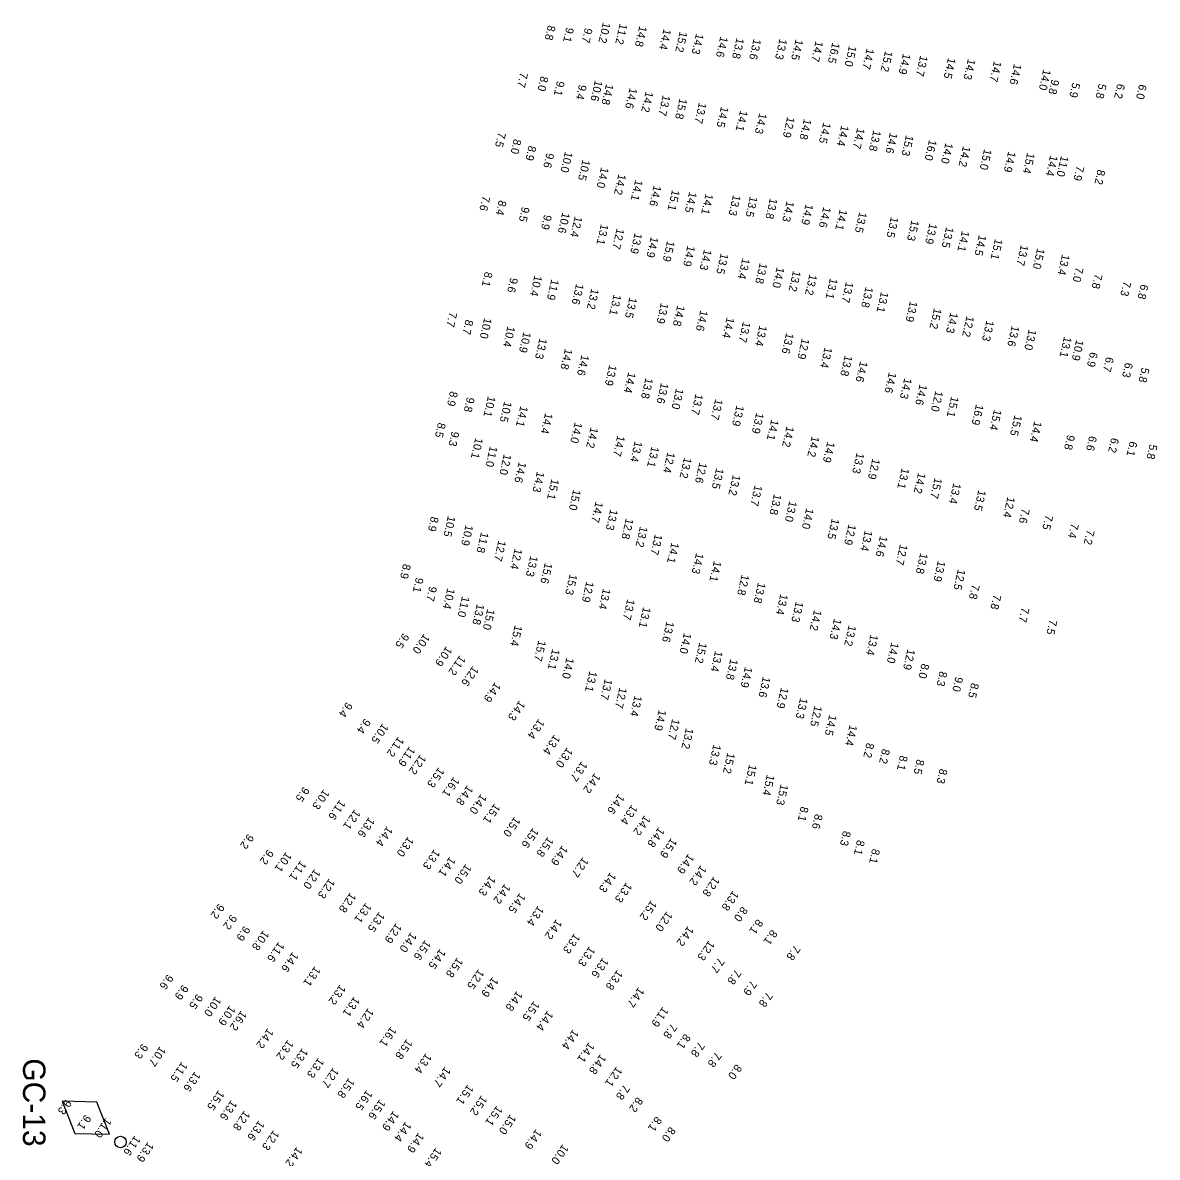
# Model space of a CAD drawing. Extents: x 815385 to 820851, y 582449 to 604245.
# Drawn here: x 820142 to 820851, y 589394 to 590103 of the extents above; entities that cross this region are included whole.
import ezdxf

# ---------------------------------------------------------------- set-up
doc = ezdxf.new("R2010")
doc.units = 0
for name, color, linetype in [('V-CHAN-AIDS', 7, 'Continuous'), ('V-TOPO-SOUN-021309', 7, 'Continuous'), ('V-TOPO-SOUN-EXCSS', 7, 'Continuous')]:
    doc.layers.add(name, color=color, linetype=linetype)

msp = doc.modelspace()

# ---------------------------------------------------------------- linework, layer by layer
at = {"layer": 'V-CHAN-AIDS'}
msp.add_lwpolyline([(820196.31, 589408.18), (820188.45, 589428.33), (820166.82, 589428.83), (820174.68, 589408.67)], close=True, dxfattribs=at)
msp.add_circle((820203.19, 589403.36), 3.6, dxfattribs=at)

# ---------------------------------------------------------------- texts
msp.add_text('GC-13', height=14, rotation=270, dxfattribs=at).set_placement((820142.31, 589455.63))
at = {"layer": 'V-TOPO-SOUN-021309'}
for s, rotation, p in [('10.2 ', 257.192, (820504.72, 590103.28)), ('11.2 ', 257.192, (820515.25, 590102.47)), ('8.8', 257.192, (820470.37, 590101.49)), ('9.1', 257.192, (820481.83, 590100.14)), ('9.7', 257.192, (820493.45, 590099.81)), ('14.8 ', 257.192, (820527.55, 590101)), ('14.4 ', 257.192, (820542.67, 590099.18)), ('15.2 ', 257.192, (820552.74, 590097.55)), ('14.3 ', 257.192, (820562.97, 590096.27)), ('14.6 ', 257.192, (820578.13, 590094.42)), ('13.8 ', 257.192, (820588.26, 590093.52)), ('13.6 ', 257.192, (820598.89, 590092.94)), ('13.3 ', 257.192, (820615.12, 590093.01)), ('14.5 ', 257.192, (820625.15, 590092.64)), ('14.7 ', 257.192, (820637.67, 590091.61)), ('16.5 ', 257.192, (820648.09, 590090.64)), ('15.0 ', 257.192, (820658.53, 590088.6)), ('14.7 ', 257.192, (820669.55, 590086.94)), ('15.2 ', 257.192, (820681.09, 590085.41)), ('14.9 ', 257.192, (820692.26, 590083.79)), ('13.7 ', 257.192, (820703.03, 590082.55)), ('14.5 ', 257.192, (820720.46, 590081.11)), ('14.3 ', 257.192, (820732.84, 590080.42)), ('14.7 ', 257.192, (820749.14, 590079.1)), ('14.6 ', 257.192, (820761.63, 590077.37)), ('7.7', 257.192, (820453.08, 590071.97)), ('8.0', 257.192, (820465.87, 590069.67)), ('10.6 ', 257.192, (820499.76, 590067.02)), ('14.0 ', 257.192, (820779.94, 590073.87)), ('9.8', 257.192, (820785.11, 590067.67)), ('9.1', 257.192, (820476.03, 590066.69)), ('9.4', 257.192, (820489.81, 590064.4)), ('14.8 ', 257.192, (820506.68, 590064.77)), ('14.6 ', 257.192, (820521.45, 590062.32)), ('14.2 ', 257.192, (820531.47, 590060.08)), ('5.9', 257.192, (820798.16, 590065.62)), ('5.8', 257.192, (820814.62, 590065.01)), ('6.2', 257.192, (820826.17, 590064.97)), ('6.0', 257.192, (820839.86, 590064.56)), ('13.7 ', 257.192, (820542.13, 590057.84)), ('15.8 ', 257.192, (820552.63, 590055.73)), ('13.7 ', 257.192, (820564.74, 590053.12)), ('14.5 ', 257.192, (820578.55, 590050.61)), ('14.1 ', 257.192, (820590.5, 590048.22)), ('14.3 ', 257.192, (820602.46, 590046.56)), ('12.9 ', 257.192, (820619.92, 590044.2)), ('14.8 ', 257.192, (820630.36, 590042.95)), ('14.5 ', 257.192, (820642.47, 590040.66)), ('14.4 ', 257.192, (820653.72, 590038.9)), ('7.5', 257.192, (820439.29, 590034.58)), ('14.7 ', 257.192, (820663.67, 590037.29)), ('13.8 ', 257.192, (820673.75, 590035.81)), ('14.6 ', 257.192, (820684.11, 590034.33)), ('15.3 ', 257.192, (820694.14, 590032.77)), ('8.0', 257.192, (820449, 590030.38)), ('8.9', 257.192, (820458.3, 590026.22)), ('16.0 ', 257.192, (820708.58, 590029.91)), ('14.0 ', 257.192, (820718.8, 590027.99)), ('14.2 ', 257.192, (820729.77, 590025.98)), ('9.6', 257.192, (820469.42, 590021.68)), ('10.0 ', 257.192, (820481.06, 590022.45)), ('10.5 ', 257.192, (820492, 590017.47)), ('15.0 ', 257.192, (820742.99, 590024.1)), ('14.9 ', 257.192, (820758.04, 590022.59)), ('15.4 ', 257.192, (820769.9, 590021.77)), ('14.4 ', 257.192, (820784.25, 590020.17)), ('11.0 ', 257.192, (820791.03, 590019.86)), ('14.0 ', 257.192, (820503.64, 590012.72)), ('7.9', 257.192, (820800.7, 590013.64)), ('8.2', 257.192, (820813.91, 590011.31)), ('14.2 ', 257.192, (820514.46, 590008.45)), ('14.1 ', 257.192, (820524.95, 590004.84)), ('14.6 ', 257.192, (820536.51, 590001.38)), ('15.1 ', 257.192, (820547.97, 589998.61)), ('14.5 ', 257.192, (820558.71, 589997.35)), ('14.1 ', 257.192, (820568.94, 589996.2)), ('7.6', 257.192, (820429.52, 589994.87)), ('8.4', 257.192, (820439.72, 589992.1)), ('13.3 ', 257.192, (820586.08, 589995.44)), ('13.5 ', 257.192, (820596.64, 589994.55)), ('13.8 ', 257.192, (820609.11, 589993.38)), ('14.3 ', 257.192, (820619.58, 589991.6)), ('14.9 ', 257.192, (820631.43, 589989.71)), ('9.5', 257.192, (820454.15, 589988.06)), ('9.9', 257.192, (820468.02, 589983.1)), ('10.6 ', 257.192, (820479.36, 589984.46)), ('12.4 ', 257.192, (820487.14, 589982.08)), ('14.6 ', 257.192, (820642.5, 589987.97)), ('14.1 ', 257.192, (820652.74, 589986.37)), ('13.5 ', 257.192, (820664.97, 589984.74)), ('13.5 ', 257.192, (820684.72, 589981.74)), ('13.1 ', 257.192, (820503.52, 589977.21)), ('15.3 ', 257.192, (820697.58, 589979.69)), ('13.9 ', 257.192, (820708.85, 589977.69)), ('13.5 ', 257.192, (820719.22, 589975.4)), ('12.7 ', 257.192, (820513.35, 589974.53)), ('13.9 ', 257.192, (820524.58, 589971.65)), ('14.9 ', 257.192, (820534.67, 589969.26)), ('14.1 ', 257.192, (820729.08, 589972.99)), ('14.5 ', 257.192, (820739.72, 589970.4)), ('15.1 ', 257.192, (820749.8, 589968.01)), ('15.9 ', 257.192, (820544.87, 589966.75)), ('14.9 ', 257.192, (820557.58, 589963.74)), ('14.3 ', 257.192, (820567.97, 589961.41)), ('13.7 ', 257.192, (820765.92, 589964.23)), ('15.0 ', 257.192, (820776.12, 589962.12)), ('13.5 ', 257.192, (820578.39, 589958.94)), ('13.4 ', 257.192, (820591.86, 589955.83)), ('13.4 ', 257.192, (820791.71, 589958.33)), ('8.1', 257.192, (820431, 589947.46)), ('13.8 ', 257.192, (820602.74, 589952.95)), ('14.0 ', 257.192, (820613.4, 589950.35)), ('13.2 ', 257.192, (820623.6, 589948.05)), ('7.0', 257.192, (820800.24, 589950.37)), ('9.6', 257.192, (820446.87, 589943.76)), ('10.4 ', 257.192, (820461.98, 589945.16)), ('11.9 ', 257.192, (820472.52, 589942.7)), ('13.6 ', 257.192, (820488.02, 589939.95)), ('13.2 ', 257.192, (820633.81, 589945.8)), ('13.1 ', 257.192, (820646.69, 589943.4)), ('13.7 ', 257.192, (820656.6, 589941.1)), ('7.8', 257.192, (820812.12, 589946.17)), ('7.3', 257.192, (820830.07, 589941.55)), ('6.8', 257.192, (820840.86, 589939.6)), ('13.2 ', 257.192, (820497.52, 589936.91)), ('13.1 ', 257.192, (820511.46, 589933.24)), ('13.8 ', 257.192, (820668.9, 589937.99)), ('13.1 ', 257.192, (820678.52, 589934.93)), ('13.5 ', 257.192, (820521.32, 589931.43)), ('13.9 ', 257.192, (820540.98, 589927.97)), ('14.8 ', 257.192, (820551.24, 589926.43)), ('13.9 ', 257.192, (820696.62, 589929.07)), ('7.7', 257.192, (820408.82, 589922.27)), ('10.0 ', 257.192, (820430.55, 589918.63)), ('14.6 ', 257.192, (820565.64, 589923.38)), ('14.4 ', 257.192, (820582.12, 589918.96)), ('15.2 ', 257.192, (820711.64, 589924.67)), ('14.3 ', 257.192, (820721.93, 589922)), ('12.2 ', 257.192, (820732.02, 589919.77)), ('8.7', 257.192, (820418.93, 589917.52)), ('10.4 ', 257.192, (820445.1, 589913.44)), ('13.7 ', 257.192, (820592.27, 589916.21)), ('13.4 ', 257.192, (820602.56, 589913.88)), ('13.3 ', 257.192, (820744.46, 589917.02)), ('13.6 ', 257.192, (820760.24, 589913.69)), ('13.0 ', 257.192, (820770.88, 589911.46)), ('10.9 ', 257.192, (820455.08, 589909.83)), ('13.3 ', 257.192, (820465.11, 589905.87)), ('13.6 ', 257.192, (820619.25, 589909.21)), ('12.9 ', 257.192, (820629.09, 589905.77)), ('13.1 ', 257.192, (820792.91, 589906.87)), ('10.9 ', 257.192, (820800.5, 589904.88)), ('14.8 ', 257.192, (820481, 589899.35)), ('13.4 ', 257.192, (820643.33, 589900.28)), ('6.9', 257.192, (820809.19, 589897.27)), ('14.6 ', 257.192, (820491.35, 589895.52)), ('13.8 ', 257.192, (820655.89, 589895.21)), ('14.6 ', 257.192, (820665.48, 589891.52)), ('6.7', 257.192, (820819.18, 589894.22)), ('6.3', 257.192, (820831.16, 589890.69)), ('13.9 ', 257.192, (820508.7, 589889.22)), ('14.4 ', 257.192, (820520.58, 589884.61)), ('14.6 ', 257.192, (820683.46, 589884.62)), ('5.8', 257.192, (820841.45, 589887.62)), ('13.8 ', 257.192, (820531.34, 589881.09)), ('13.6 ', 257.192, (820541.02, 589877.99)), ('14.3 ', 257.192, (820693.1, 589880.96)), ('14.6 ', 257.192, (820702.65, 589877.06)), ('8.9', 257.192, (820409.28, 589872.79)), ('9.8', 257.192, (820419.78, 589869.12)), ('10.1 ', 257.192, (820432.89, 589869.73)), ('13.0 ', 257.192, (820550.43, 589874.53)), ('13.7 ', 257.192, (820562.62, 589871.1)), ('12.0 ', 257.192, (820712.54, 589873.03)), ('15.1 ', 257.192, (820722.4, 589869.54)), ('10.5 ', 257.192, (820443.06, 589866.39)), ('14.1 ', 257.192, (820453.18, 589863.53)), ('13.7 ', 257.192, (820574.95, 589867.9)), ('13.9 ', 257.192, (820588.21, 589863.94)), ('16.9 ', 257.192, (820737.9, 589864.59)), ('15.4 ', 257.192, (820749.16, 589861.38)), ('14.4 ', 257.192, (820468.62, 589859.16)), ('13.9 ', 257.192, (820600.55, 589859.31)), ('14.1 ', 257.192, (820609.92, 589855.08)), ('15.5 ', 257.192, (820761.95, 589857.86)), ('8.5', 257.192, (820401.73, 589853.17)), ('9.3', 257.192, (820410.18, 589847.74)), ('14.0 ', 257.192, (820487.1, 589853.34)), ('14.2 ', 257.192, (820497.06, 589850.22)), ('14.2 ', 257.192, (820619.5, 589850.86)), ('14.4 ', 257.192, (820774.3, 589853.99)), ('10.1 ', 257.192, (820425.04, 589843.67)), ('14.7 ', 257.192, (820513.79, 589845.04)), ('13.4 ', 257.192, (820524.62, 589841.57)), ('14.2 ', 257.192, (820635.27, 589844.69)), ('14.9 ', 257.192, (820644.95, 589841.18)), ('9.8', 257.192, (820794.92, 589845.53)), ('6.6', 257.192, (820808.66, 589844.89)), ('6.2', 257.192, (820822.43, 589843.7)), ('6.1', 257.192, (820833.91, 589841.48)), ('11.0 ', 257.192, (820434.14, 589838.45)), ('12.0 ', 257.192, (820442.83, 589833.48)), ('13.1 ', 257.192, (820535.13, 589838.25)), ('12.4 ', 257.192, (820545.08, 589834.71)), ('13.3 ', 257.192, (820663.31, 589834.3)), ('5.8', 257.192, (820846.4, 589839.64)), ('14.6 ', 257.192, (820452.16, 589828.58)), ('13.2 ', 257.192, (820555.48, 589831.36)), ('12.6 ', 257.192, (820565.06, 589828.28)), ('12.9 ', 257.192, (820673.15, 589830.7)), ('14.3 ', 257.192, (820463.51, 589822.56)), ('13.5 ', 257.192, (820575.56, 589824.7)), ('13.2 ', 257.192, (820585.95, 589820.57)), ('13.1 ', 257.192, (820691.47, 589824.74)), ('14.2 ', 257.192, (820701.74, 589821.85)), ('15.7 ', 257.192, (820712, 589818.66)), ('15.1 ', 257.192, (820472.61, 589817.99)), ('13.7 ', 257.192, (820599.6, 589814.08)), ('13.4 ', 257.192, (820723.77, 589815.4)), ('15.0 ', 257.192, (820486.21, 589811.36)), ('13.8 ', 257.192, (820611.65, 589808.52)), ('13.5 ', 257.192, (820739.39, 589811.01)), ('12.4 ', 257.192, (820757.55, 589806.79)), ('14.7 ', 257.192, (820500.17, 589803.77)), ('13.3 ', 257.192, (820509.34, 589798.93)), ('13.0 ', 257.192, (820621.23, 589804.16)), ('14.0 ', 257.192, (820631.8, 589799.66)), ('7.6', 257.192, (820766.63, 589799.58)), ('8.9', 257.192, (820397.35, 589794.52)), ('10.5 ', 257.192, (820407.86, 589794.82)), ('12.8 ', 257.192, (820519.12, 589793.35)), ('13.5 ', 257.192, (820647.79, 589793.26)), ('7.5', 257.192, (820781.28, 589795.54)), ('10.9 ', 257.192, (820418.93, 589789.25)), ('11.8 ', 257.192, (820428.59, 589784.73)), ('13.2 ', 257.192, (820527.94, 589788.33)), ('13.7 ', 257.192, (820537.2, 589783.42)), ('12.9 ', 257.192, (820658.26, 589789.62)), ('13.4 ', 257.192, (820668.45, 589785.81)), ('7.4', 257.192, (820797.35, 589790.28)), ('7.2', 257.192, (820807.19, 589786.22)), ('12.7 ', 257.192, (820439.41, 589779.54)), ('14.1 ', 257.192, (820547.58, 589778.27)), ('14.6 ', 257.192, (820677.91, 589782.35)), ('12.7 ', 257.192, (820690.44, 589777.13)), ('12.4 ', 257.192, (820449.61, 589774.47)), ('13.3 ', 257.192, (820459.39, 589769.89)), ('14.3 ', 257.192, (820562.98, 589771.67)), ('13.8 ', 257.192, (820703.08, 589771.64)), ('8.9', 257.192, (820379.92, 589764.94)), ('15.6 ', 257.192, (820468.45, 589765.56)), ('14.1 ', 257.192, (820574.09, 589766.74)), ('13.9 ', 257.192, (820714.07, 589766.79)), ('9.1', 257.192, (820387.85, 589756.37)), ('15.3 ', 257.192, (820483.97, 589758.49)), ('12.8 ', 257.192, (820591.46, 589758.22)), ('12.5 ', 257.192, (820726.57, 589761.56)), ('9.7', 257.192, (820396.24, 589750.93)), ('10.4 ', 257.192, (820407.5, 589749.64)), ('12.9 ', 257.192, (820494.36, 589753.89)), ('13.4 ', 257.192, (820504.82, 589749.5)), ('13.8 ', 257.192, (820601.7, 589753.26)), ('7.8', 257.192, (820735.41, 589752.16)), ('11.0 ', 257.192, (820416.69, 589744.63)), ('13.7 ', 257.192, (820519.97, 589742.84)), ('13.4 ', 257.192, (820615.65, 589746.07)), ('13.3 ', 257.192, (820625.3, 589741.4)), ('7.8', 257.192, (820748.85, 589745.77)), ('13.8 ', 257.192, (820425.96, 589739.85)), ('15.0 ', 257.192, (820432.48, 589736.65)), ('13.1 ', 257.192, (820529.89, 589737.89)), ('14.2 ', 257.192, (820636.71, 589736.13)), ('7.7', 257.192, (820766.42, 589737.72)), ('15.4 ', 257.192, (820449.62, 589726.53)), ('13.6 ', 257.192, (820544.5, 589728.92)), ('14.3 ', 257.192, (820649.17, 589730.68)), ('13.2 ', 257.192, (820658.3, 589726.51)), ('7.5', 257.192, (820783.85, 589730.06)), ('9.5', 234.911, (820379.97, 589721.71)), ('10.0 ', 234.911, (820392.96, 589721.24)), ('14.0 ', 257.192, (820555.37, 589721.77)), ('13.4 ', 257.192, (820671.99, 589720.77)), ('10.9 ', 234.911, (820406.94, 589713.43)), ('15.7 ', 257.192, (820464.4, 589717.07)), ('15.2 ', 257.192, (820565, 589715.74)), ('14.0 ', 257.192, (820684.95, 589715.79)), ('11.2 ', 234.911, (820415.33, 589707.8)), ('13.1 ', 257.192, (820473.07, 589711.72)), ('14.0 ', 257.192, (820481.98, 589706.22)), ('13.4 ', 257.192, (820574.83, 589710.52)), ('13.8 ', 257.192, (820584.41, 589705.44)), ('12.9 ', 257.192, (820695.1, 589711.66)), ('12.6 ', 234.911, (820423.45, 589701.09)), ('14.9 ', 257.192, (820593.48, 589700.54)), ('8.0', 257.192, (820703.86, 589702.68)), ('14.9 ', 234.911, (820437.37, 589691.02)), ('13.1 ', 257.192, (820496.34, 589697.91)), ('13.7 ', 257.192, (820505.9, 589692.98)), ('13.6 ', 257.192, (820604.71, 589694.39)), ('8.3', 257.192, (820715.17, 589697.8)), ('9.0', 257.192, (820725.03, 589694.39)), ('12.7 ', 257.192, (820515.03, 589687.61)), ('12.9 ', 257.192, (820616.06, 589687.59)), ('8.5', 257.192, (820734.94, 589690.48)), ('9.4', 234.911, (820344.63, 589678.63)), ('14.3 ', 234.911, (820452.53, 589679.54)), ('13.4 ', 257.192, (820524.48, 589682.61)), ('13.3 ', 257.192, (820628.01, 589681.14)), ('14.9 ', 257.192, (820539.63, 589673.68)), ('12.5 ', 257.192, (820637.01, 589676.25)), ('14.5 ', 257.192, (820646.15, 589670.59)), ('9.4', 234.911, (820355.92, 589668.39)), ('10.5 ', 234.911, (820367.09, 589665.28)), ('13.4 ', 234.911, (820464.66, 589668.11)), ('12.7 ', 257.192, (820548.03, 589668.08)), ('14.4 ', 257.192, (820658.91, 589664.24)), ('11.2 ', 234.911, (820376.83, 589656.9)), ('13.4 ', 234.911, (820474.37, 589658.19)), ('13.2 ', 257.192, (820556.62, 589662.27)), ('11.9 ', 234.911, (820383.83, 589650.87)), ('13.0 ', 234.911, (820482.37, 589650.16)), ('13.3 ', 257.192, (820573.79, 589652.04)), ('8.2', 257.192, (820669.47, 589653.07)), ('8.2', 257.192, (820679.28, 589649.35)), ('12.2 ', 234.911, (820390.63, 589645.84)), ('13.7 ', 234.911, (820491.43, 589641.59)), ('15.2 ', 257.192, (820582.55, 589646.87)), ('8.1', 257.192, (820690.46, 589645.22)), ('8.5', 257.192, (820700.88, 589642.78)), ('15.3 ', 234.911, (820402.05, 589637.73)), ('14.2 ', 234.911, (820499.59, 589634.21)), ('15.1 ', 257.192, (820596.14, 589639.52)), ('8.3', 257.192, (820715.24, 589636.91)), ('16.1 ', 234.911, (820411.48, 589631.8)), ('15.4 ', 257.192, (820607.25, 589633.14)), ('9.5', 234.911, (820317.66, 589625.76)), ('10.3 ', 234.911, (820330.24, 589624.07)), ('14.8 ', 234.911, (820420.03, 589626.6)), ('14.0 ', 234.911, (820428.52, 589621.15)), ('14.6 ', 234.911, (820514.57, 589621.2)), ('15.3 ', 257.192, (820615.8, 589627.14)), ('11.6 ', 234.911, (820340.28, 589617.52)), ('15.1 ', 234.911, (820436.98, 589615.21)), ('13.4 ', 234.911, (820522.79, 589614.49)), ('8.1', 257.192, (820628.45, 589613.32)), ('12.1 ', 234.911, (820349.58, 589611.51)), ('13.6 ', 234.911, (820358.53, 589606.59)), ('15.0 ', 234.911, (820449.53, 589606.92)), ('14.2 ', 234.911, (820530.84, 589607.81)), ('8.6', 257.192, (820637.27, 589608.6)), ('14.4 ', 234.911, (820369.9, 589600.97)), ('15.6 ', 234.911, (820461.02, 589599.98)), ('14.8 ', 234.911, (820539.63, 589600.41)), ('9.2', 234.911, (820282.95, 589596.26)), ('13.0 ', 234.911, (820382.94, 589594.51)), ('15.8 ', 234.911, (820470.31, 589594.35)), ('15.9 ', 234.911, (820547.43, 589593.65)), ('8.3', 257.192, (820654.86, 589598.06)), ('8.1', 257.192, (820663.59, 589592.36)), ('9.2', 234.911, (820295.31, 589586.54)), ('10.1 ', 234.911, (820306.71, 589584.9)), ('13.3 ', 234.911, (820399.32, 589586.57)), ('14.9 ', 234.911, (820479.27, 589588.96)), ('8.1', 257.192, (820673.06, 589586.91)), ('11.1 ', 234.911, (820315.77, 589579.5)), ('14.1 ', 234.911, (820409.02, 589581.97)), ('12.7 ', 234.911, (820492.17, 589581.62)), ('14.9 ', 234.911, (820558.12, 589583.8)), ('12.0 ', 234.911, (820324.59, 589574.28)), ('15.0 ', 234.911, (820419.03, 589577.41)), ('14.3 ', 234.911, (820509.36, 589572.22)), ('14.2 ', 234.911, (820565.89, 589576.6)), ('12.3 ', 234.911, (820333.69, 589568.39)), ('14.3 ', 234.911, (820434.14, 589570.09)), ('14.2 ', 234.911, (820443.42, 589565.07)), ('13.3 ', 234.911, (820519.33, 589565.84)), ('12.8 ', 234.911, (820574.07, 589569.56)), ('12.8 ', 234.911, (820346.86, 589559.55)), ('14.5 ', 234.911, (820452.76, 589559.27)), ('13.8 ', 234.911, (820586.04, 589560.72)), ('9.2', 234.911, (820264.57, 589552.66)), ('13.1 ', 234.911, (820356.52, 589553.12)), ('13.4 ', 234.911, (820464.27, 589551.26)), ('15.2 ', 234.911, (820534.88, 589554.72)), ('8.0', 234.911, (820591.6, 589550.89)), ('9.2', 234.911, (820272.38, 589545.88)), ('13.5 ', 234.911, (820364.84, 589547.44)), ('14.2 ', 234.911, (820475.58, 589542.83)), ('12.0 ', 234.911, (820544.63, 589547.8)), ('8.1', 234.911, (820601.2, 589543)), ('9.9', 234.911, (820280.65, 589538.79)), ('10.8 ', 234.911, (820292.5, 589535.95)), ('12.9 ', 234.911, (820375.46, 589540.41)), ('14.2 ', 234.911, (820557.88, 589538.62)), ('8.1', 234.911, (820610.11, 589536.39)), ('11.6 ', 234.911, (820302.06, 589528.71)), ('14.0 ', 234.911, (820384.74, 589534.74)), ('15.6 ', 234.911, (820393.63, 589529.91)), ('13.3 ', 234.911, (820486.9, 589534.02)), ('12.3 ', 234.911, (820570.94, 589529.63)), ('14.6 ', 234.911, (820310.86, 589522.47)), ('14.5 ', 234.911, (820402.86, 589524.38)), ('13.3 ', 234.911, (820496.29, 589525.97)), ('7.8', 234.911, (820624.44, 589526.71)), ('15.8 ', 234.911, (820413.73, 589518.95)), ('13.6 ', 234.911, (820504.64, 589518.85)), ('7.7', 234.911, (820577.04, 589518.87)), ('9.6', 234.911, (820232.64, 589508.52)), ('13.1 ', 234.911, (820324.67, 589513.48)), ('12.5 ', 234.911, (820426.98, 589511.7)), ('14.9 ', 234.911, (820435.79, 589506.77)), ('13.8 ', 234.911, (820513.64, 589511.17)), ('7.8', 234.911, (820587.5, 589511.62)), ('9.9', 234.911, (820242.06, 589502.03)), ('13.2 ', 234.911, (820340.39, 589501.99)), ('14.7 ', 234.911, (820526.99, 589500.41)), ('7.9', 234.911, (820597.29, 589504.68)), ('9.5', 234.911, (820251.08, 589496.25)), ('10.0 ', 234.911, (820262.6, 589494.59)), ('13.1 ', 234.911, (820349.25, 589494.53)), ('14.8 ', 234.911, (820451.03, 589498.06)), ('7.8', 234.911, (820607.14, 589497.5)), ('10.9 ', 234.911, (820271.46, 589488.96)), ('16.2 ', 234.911, (820278.67, 589485.77)), ('12.4 ', 234.911, (820358.03, 589487.35)), ('15.5 ', 234.911, (820461.55, 589491.8)), ('14.4 ', 234.911, (820470.11, 589485.77)), ('11.9 ', 234.911, (820542.15, 589488.13)), ('14.2 ', 234.911, (820295.28, 589474.72)), ('16.1 ', 234.911, (820372.19, 589475.78)), ('14.4 ', 234.911, (820486.09, 589474.08)), ('7.8', 234.911, (820547.42, 589477.75)), ('8.1', 234.911, (820555.89, 589471.35)), ('9.3', 234.911, (820216.85, 589465.2)), ('13.2 ', 234.911, (820307.77, 589467.5)), ('15.8 ', 234.911, (820382.09, 589467.97)), ('14.1 ', 234.911, (820495.89, 589465.91)), ('7.8', 234.911, (820564.69, 589466.27)), ('10.7 ', 234.911, (820227.96, 589463.51)), ('13.5 ', 234.911, (820316.84, 589462.31)), ('13.4 ', 234.911, (820394.09, 589459.15)), ('14.8 ', 234.911, (820503.17, 589458.6)), ('7.8', 234.911, (820575.19, 589459.98)), ('11.5 ', 234.911, (820241.59, 589453.79)), ('13.3 ', 234.911, (820326.89, 589456.28)), ('12.7 ', 234.911, (820336.17, 589450.19)), ('14.7 ', 234.911, (820405.99, 589450.65)), ('12.1 ', 234.911, (820513.24, 589450.82)), ('8.0', 234.911, (820587.9, 589452.35)), ('13.6 ', 234.911, (820249.71, 589447.73)), ('15.8 ', 234.911, (820345.93, 589443.7)), ('15.5 ', 234.911, (820264.52, 589436.09)), ('16.5 ', 234.911, (820357.09, 589436.16)), ('15.1 ', 234.911, (820420.26, 589439.58)), ('7.8', 234.911, (820517.87, 589439.57)), ('13.6 ', 234.911, (820272.46, 589429.8)), ('15.6 ', 234.911, (820365.23, 589430.33)), ('15.2 ', 234.911, (820428.84, 589432.82)), ('8.2', 234.911, (820526.11, 589431.82)), ('12.8 ', 234.911, (820280.63, 589423.32)), ('14.9 ', 234.911, (820373.78, 589423.14)), ('15.1 ', 234.911, (820438.38, 589426.37)), ('9.1', 234.911, (820181.25, 589420.83)), ('13.6 ', 234.911, (820289.69, 589417.13)), ('14.4 ', 234.911, (820381.43, 589416.42)), ('15.0 ', 234.911, (820446.83, 589420.98)), ('8.1', 234.911, (820537.9, 589419.71)), ('11.6 ', 234.911, (820212.23, 589407.7)), ('12.3 ', 234.911, (820298.87, 589411.09)), ('14.9 ', 234.911, (820389.47, 589409.51)), ('14.9 ', 234.911, (820462.91, 589411.7)), ('8.0', 234.911, (820546.52, 589413.29)), ('13.9 ', 234.911, (820220.43, 589403.7)), ('14.2 ', 234.911, (820313.44, 589400.72)), ('10.0 ', 234.911, (820479.6, 589402.29)), ('15.4 ', 234.911, (820400.33, 589400.13))]:
    msp.add_text(s, height=5, rotation=rotation, dxfattribs=at).set_placement(p)
at = {"layer": 'V-TOPO-SOUN-EXCSS'}
for s, p in [('9.3', (820169.01, 589430.34)), ('11.0 ', (820194.05, 589418.88))]:
    msp.add_text(s, height=5, rotation=234.911, dxfattribs=at).set_placement(p)

doc.saveas('drawing.dxf')
